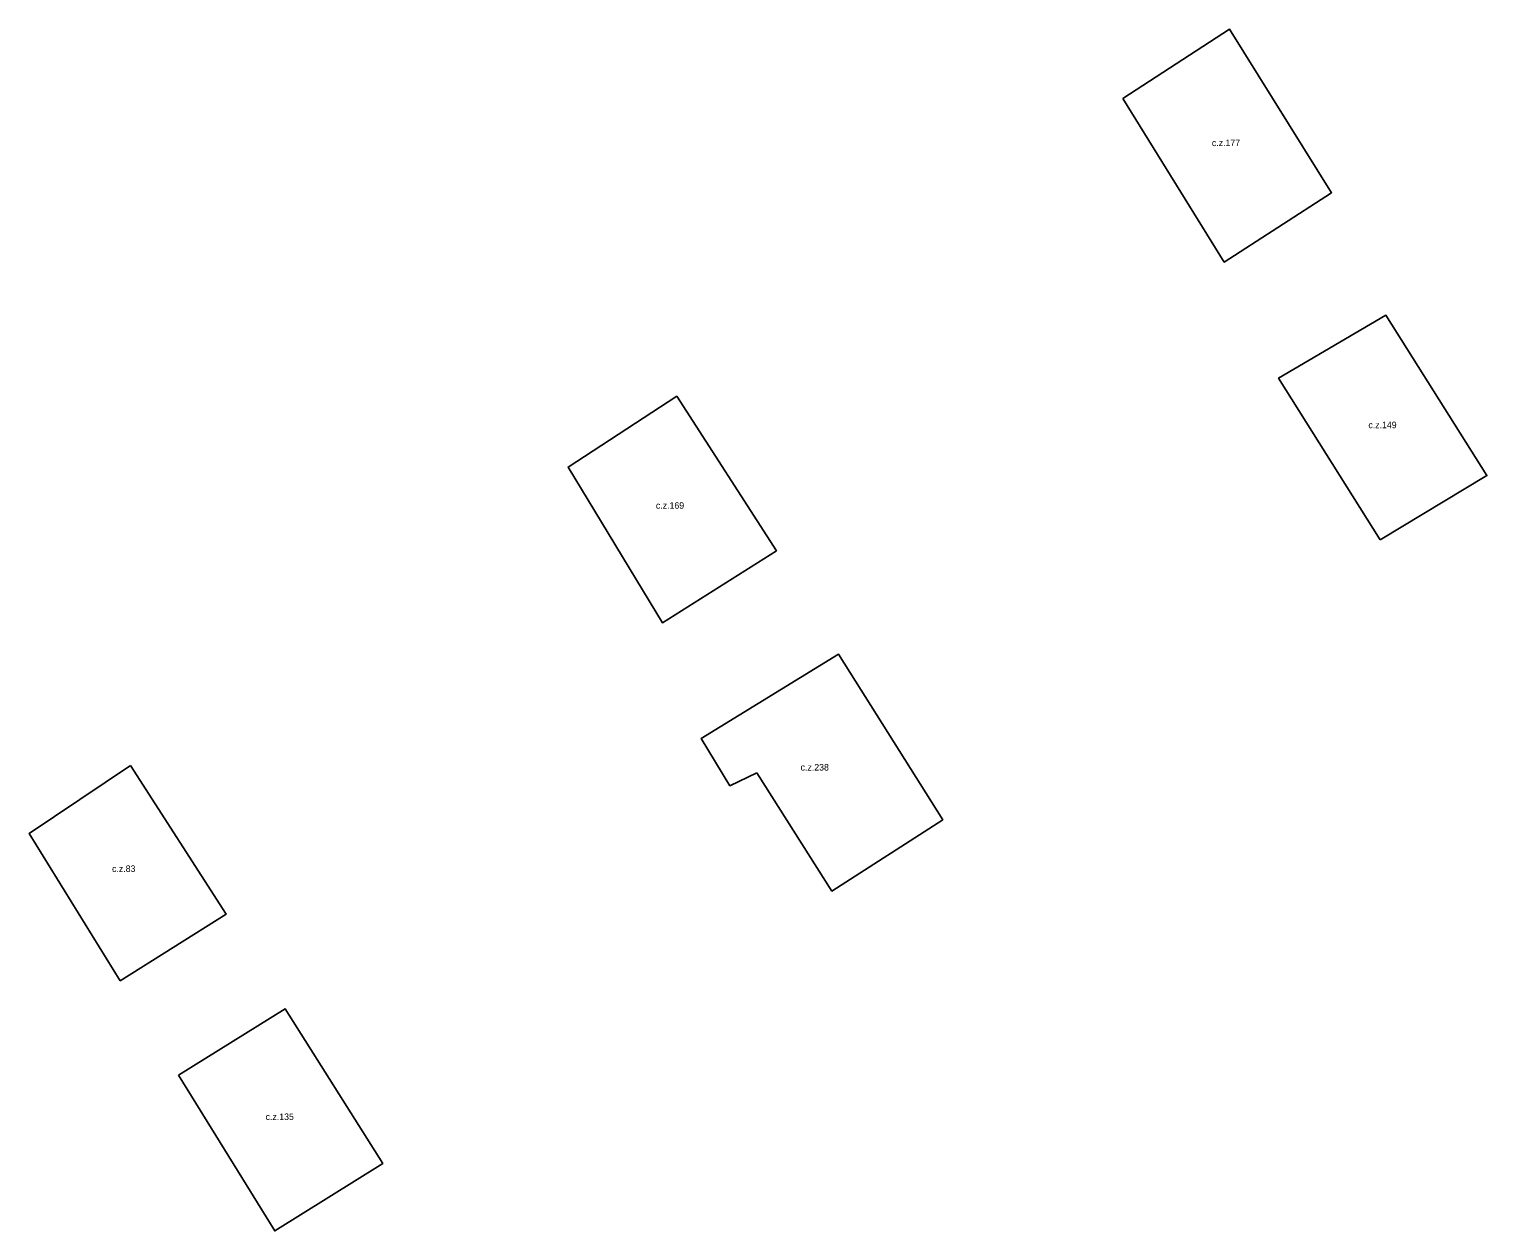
# Model space of a CAD drawing. Extents: x -600391 to -599491, y -1160176 to -1159402.
# Drawn here: x -599742.14 to -599719.88, y -1159437.19 to -1159418.83 of the extents above; entities that cross this region are included whole.
import ezdxf

# ---------------------------------------------------------------- set-up
doc = ezdxf.new("R2010")
doc.units = 0
for name, color, linetype in [('Level 24', 7, 'Continuous'), ('Level 61', 7, 'Continuous'), ('Level 62', 7, 'Continuous')]:
    doc.layers.add(name, color=color, linetype=linetype)

msp = doc.modelspace()

# ---------------------------------------------------------------- linework, layer by layer
at = {"layer": 'Level 61'}
for points in [[(-599725.44, -1159419.89), (-599723.81, -1159418.83)], [(-599723.81, -1159418.83), (-599722.25, -1159421.33)], [(-599723.89, -1159422.39), (-599725.44, -1159419.89)], [(-599722.25, -1159421.33), (-599723.89, -1159422.39)], [(-599723.06, -1159424.16), (-599721.42, -1159423.2)], [(-599721.42, -1159423.2), (-599719.88, -1159425.65)], [(-599721.51, -1159426.63), (-599723.06, -1159424.16)], [(-599733.91, -1159425.52), (-599732.25, -1159424.44)], [(-599732.25, -1159424.44), (-599730.73, -1159426.8)], [(-599732.47, -1159427.9), (-599733.91, -1159425.52)], [(-599719.88, -1159425.65), (-599721.51, -1159426.63)], [(-599730.73, -1159426.8), (-599732.47, -1159427.9)], [(-599731.88, -1159429.67), (-599729.78, -1159428.38)], [(-599729.78, -1159428.38), (-599728.19, -1159430.91)], [(-599731.44, -1159430.39), (-599731.88, -1159429.67)], [(-599742.14, -1159431.12), (-599740.59, -1159430.08)], [(-599740.59, -1159430.08), (-599739.13, -1159432.35)], [(-599731.03, -1159430.19), (-599731.44, -1159430.39)], [(-599729.88, -1159432), (-599731.03, -1159430.19)], [(-599728.19, -1159430.91), (-599729.88, -1159432)], [(-599740.75, -1159433.37), (-599742.14, -1159431.12)], [(-599739.13, -1159432.35), (-599740.75, -1159433.37)], [(-599739.86, -1159434.81), (-599738.23, -1159433.8)], [(-599738.23, -1159433.8), (-599736.74, -1159436.16)], [(-599738.39, -1159437.19), (-599739.86, -1159434.81)], [(-599736.74, -1159436.16), (-599738.39, -1159437.19)]]:
    msp.add_lwpolyline(points, dxfattribs=at)
at = {"layer": 'Level 62'}
for points in [[(-599725.44, -1159419.89), (-599723.81, -1159418.83), (-599722.25, -1159421.33), (-599723.89, -1159422.39), (-599725.44, -1159419.89)], [(-599721.51, -1159426.63), (-599723.06, -1159424.16), (-599721.42, -1159423.2), (-599719.88, -1159425.65), (-599721.51, -1159426.63)], [(-599732.25, -1159424.44), (-599730.73, -1159426.8), (-599732.47, -1159427.9), (-599733.91, -1159425.52), (-599732.25, -1159424.44)], [(-599731.03, -1159430.19), (-599731.44, -1159430.39), (-599731.88, -1159429.67), (-599729.78, -1159428.38), (-599728.19, -1159430.91), (-599729.88, -1159432), (-599731.03, -1159430.19)], [(-599740.59, -1159430.08), (-599739.13, -1159432.35), (-599740.75, -1159433.37), (-599742.14, -1159431.12), (-599740.59, -1159430.08)], [(-599739.86, -1159434.81), (-599738.23, -1159433.8), (-599736.74, -1159436.16), (-599738.39, -1159437.19), (-599739.86, -1159434.81)]]:
    msp.add_lwpolyline(points, dxfattribs=at)

# ---------------------------------------------------------------- texts
at = {"layer": 'Level 24'}
for s, p in [('c.z.177', (-599724.079, -1159420.617)), ('c.z.149', (-599721.689, -1159424.927)), ('c.z.169', (-599732.569, -1159426.157)), ('c.z.238', (-599730.359, -1159430.157)), ('c.z.83', (-599740.874, -1159431.707)), ('c.z.135', (-599738.529, -1159435.497))]:
    msp.add_text(s, height=0.1, dxfattribs=at).set_placement(p)

doc.saveas('drawing.dxf')
